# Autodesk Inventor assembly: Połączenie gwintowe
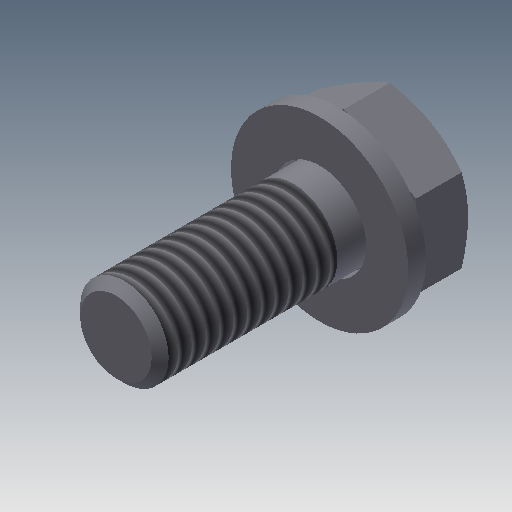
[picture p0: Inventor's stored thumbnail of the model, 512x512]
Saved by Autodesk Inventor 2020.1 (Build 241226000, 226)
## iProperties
Created: 2010-10
Part Number: Połączenie gwintowe
Document SubType Name: Assembly
Designer: F.Stasiak
ClientObjectVersion: 1
Manager: www.cadconsulting.pl
Company: Fabian Stasiak CAD Consulting
Author: F.Stasiak
Subject: Zbiór ćwiczeń. Autodesk Inventor 2020. Kurs podstawowy
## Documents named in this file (3)
- C:\2020_Kurs_podstawowy\R9 Zarządzanie plikami\369-000\Design Accelerator\Połączenie gwintowe6.iam
- C:\2020_Kurs_podstawowy\Zasoby\Content Center Files\pl-PL\ISO 7089\ISO 7089 - 8 - 140 HV(1).ipt
- C:\2020_Kurs_podstawowy\Zasoby\Content Center Files\pl-PL\ISO 4017(1)\ISO 4017 - M8 x 20ISO.ipt
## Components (2 placed, 2 different names)
1. ISO 7089 8 - 140 HV:1
2. ISO 4017 M8 x 20:1
